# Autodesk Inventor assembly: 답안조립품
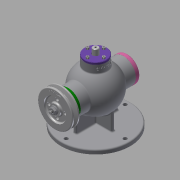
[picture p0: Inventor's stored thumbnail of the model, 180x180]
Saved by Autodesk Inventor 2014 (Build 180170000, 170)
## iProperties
Created: 2020-08
Part Number: 답안조립품
Document SubType Name: Assembly
Designer: kh
Author: kh
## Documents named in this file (18)
- C:\Users\kh\Desktop\700806V1029\답안조립품.iam
- C:\Users\kh\Desktop\700806V1029\본체.ipt
- C:\Users\kh\Desktop\700806V1029\V-벨트풀리.ipt
- C:\Users\kh\Desktop\700806V1029\너트 M8.ipt
- C:\Users\kh\Desktop\700806V1029\뒤커버.ipt
- C:\Users\kh\Desktop\700806V1029\멈춤링 15x1.ipt
- C:\Users\kh\Desktop\700806V1029\멈춤링 35x1.6.ipt
- 멈춤링 35x1.6.ipt
- C:\Users\kh\Desktop\700806V1029\베어링 6202.ipt
- 베어링 6202.ipt
- C:\Users\kh\Desktop\700806V1029\볼트 M4.ipt
- C:\Users\kh\Desktop\700806V1029\상부커버.ipt
- C:\Users\kh\Desktop\700806V1029\슬라이드.ipt
- C:\Users\kh\Desktop\700806V1029\앞커버.ipt
- C:\Users\kh\Desktop\700806V1029\편심축.ipt
- C:\Users\kh\Desktop\700806V1029\오일 실 15 30 7.ipt
- C:\Users\kh\Desktop\700806V1029\칼라.ipt
- C:\Users\kh\Desktop\700806V1029\키 3x3x12.ipt
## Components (1 placed, 1 different names)
1. V-벨트풀리:1 — Insert:13, Mate:12, Insert:14
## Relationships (3: Insert 2, Mate 1)
- Insert:13: V-벨트풀리:1
- Mate:12: V-벨트풀리:1
- Insert:14: V-벨트풀리:1
